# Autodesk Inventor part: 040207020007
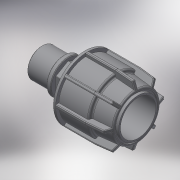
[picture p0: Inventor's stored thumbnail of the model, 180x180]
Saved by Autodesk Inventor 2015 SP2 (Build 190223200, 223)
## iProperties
Created: 2017-08
Part Number: 040207020007
Material: Generic
Description: PLASSON IRRIFIT ADAPTOR 20-3/4"M
Document SubType Name: Modeling
Designer: KIM
Density: 1 g/cm^3
Appearance: Default
Author: KIM
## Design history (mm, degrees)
derived "040207.ipt"
feature "Solid1::040207.ipt"
tag "TaggingFeature1"
body "Solid1"
other parameters: "d5" = 30.8, "d6" = 14.52, "d10" = 39, "d22" = 26.441, "d24" = 1.518, "d25" = 35.1, "d26" = 31.2, "d31" = 0.8, "d49" = 1.95, "d50" = 0, "d58" = 0.4, "d61" = 360 deg, "d78" = 5 deg, "d80" = 22, "d81" = 33, "d82" = 1.98, "d84" = 5 deg, "d85" = 70 deg, "d86" = 37.05, "d87" = 0.33, "d88" = 0, "d89" = 33.15, "d90" = 3.3, "d91" = 0, "d99" = 26.441, "d100" = 17, "d101" = 3.4, "d102" = 66, "d103" = 31.7292, "d104" = 0.52882, "d108" = 0, "d109" = 0.26441, "d112" = 21.1528, "d113" = 24.64, "E_" = 39, "H_" = 66, "l_nut" = 30.8, "l_" = 17, "R_" = 26.441
